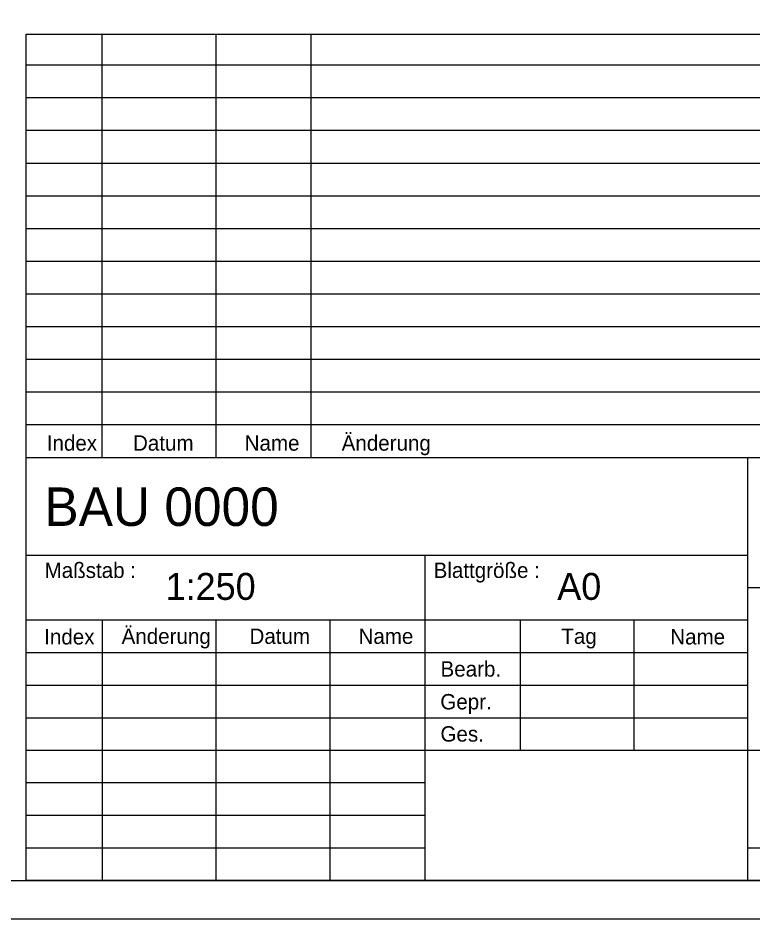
# Model space of a CAD drawing. Extents: x 0 to 297, y 0 to 210.
# Drawn here: x 251.26 to 275.16, y 0 to 29.27 of the extents above; entities that cross this region are included whole.
import ezdxf

# ---------------------------------------------------------------- set-up
doc = ezdxf.new("R2010")
doc.units = 0
doc.layers.add('90_Plankopf', color=7, linetype='Continuous')

msp = doc.modelspace()

# ---------------------------------------------------------------- linework, layer by layer
at = {"layer": '90_Plankopf'}
for p, q in [((251.53, 14.998), (251.53, 28.745)), ((251.53, 28.745), (296, 28.745)), ((254.001, 14.998), (254.001, 28.745)), ((257.707, 14.998), (257.707, 28.745)), ((260.795, 14.998), (260.795, 28.745)), ((251.53, 27.748), (296, 27.748)), ((251.53, 26.685), (296, 26.685)), ((251.53, 25.623), (296, 25.623)), ((251.53, 24.56), (296, 24.56)), ((251.53, 23.498), (296, 23.498)), ((251.53, 22.435), (296, 22.435)), ((251.53, 21.373), (296, 21.373)), ((251.53, 20.31), (296, 20.31)), ((251.53, 19.248), (296, 19.248)), ((251.53, 18.185), (296, 18.185)), ((251.53, 17.123), (296, 17.123)), ((251.53, 16.06), (296, 16.06)), ((251.53, 14.998), (296, 14.998)), ((251.53, 1.25), (251.53, 14.998)), ((251.53, 14.998), (296, 14.998)), ((275, 1.25), (275, 14.998)), ((251.53, 11.825), (275, 11.825)), ((264.5, 1.25), (264.5, 11.825)), ((275, 10.768), (296, 10.768)), ((251.53, 9.718), (275, 9.718)), ((254.001, 9.71), (254.001, 1.25)), ((257.707, 1.25), (257.707, 9.71)), ((261.412, 1.25), (261.412, 9.71)), ((267.589, 9.71), (267.589, 5.48)), ((271.295, 5.48), (271.295, 9.71)), ((251.53, 8.658), (275, 8.658)), ((251.53, 7.595), (275, 7.595)), ((251.53, 6.538), (275, 6.538)), ((251.53, 5.48), (275, 5.48)), ((251.53, 5.48), (275, 5.48)), ((264.5, 5.48), (275, 5.48)), ((275, 5.48), (296, 5.48)), ((264.5, 4.423), (251.53, 4.423)), ((264.5, 3.365), (251.53, 3.365)), ((251.53, 2.308), (264.5, 2.308)), ((275, 2.308), (296, 2.308)), ((296, 1.25), (251.53, 1.25)), ((251.53, 1.25), (264.5, 1.25)), ((254.45, 1.25), (296, 1.25)), ((254.45, 1.25), (296, 1.25))]:
    msp.add_line(p, q, dxfattribs=at)
for points in [[(0, 0), (297.25, 0), (297.25, 210.25), (0, 210.25)], [(6.25, 1.25), (296, 1.25), (296, 209), (6.25, 209)]]:
    msp.add_lwpolyline(points, close=True, dxfattribs=at)

# ---------------------------------------------------------------- texts
for s, height, p in [('Änderung', 0.5, (261.789, 15.214)), ('Index', 0.5, (252.201, 15.214)), ('Datum', 0.5, (255.004, 15.214)), ('Name', 0.5, (258.635, 15.214)), ('BAU 0000      ', 1.25, (252.123, 12.769)), ('Maßstab :', 0.5, (252.129, 11.079)), ('Blattgröße :', 0.49998, (264.779, 11.079)), ('1:250    ', 0.875, (256.065, 10.367)), ('A0       ', 0.875, (268.8, 10.367)), ('Index', 0.5, (252.117, 8.918)), ('Änderung', 0.5, (254.634, 8.937)), ('Datum', 0.5, (258.792, 8.937)), ('Name', 0.5, (262.337, 8.937)), ('Tag', 0.5, (268.931, 8.937)), ('Name', 0.5, (272.473, 8.918)), ('Bearb.', 0.5, (265.004, 7.873)), ('Gepr.', 0.5, (264.997, 6.808)), ('Ges.', 0.5, (265.001, 5.762))]:
    msp.add_text(s, height=height, dxfattribs=at).set_placement(p)

doc.saveas('drawing.dxf')
